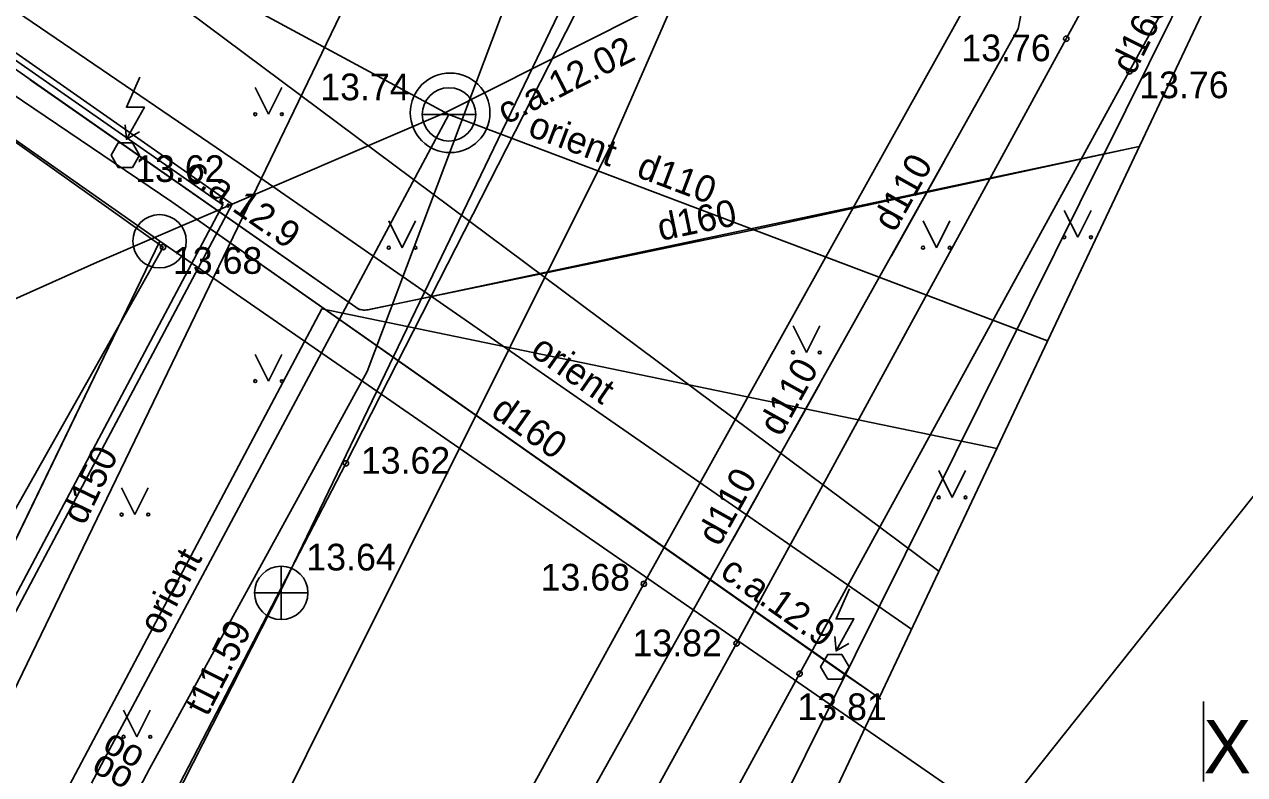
# Model space of a CAD drawing. Extents: x 503904 to 504094, y 304688 to 304960.
# Drawn here: x 504027.93 to 504050.77, y 304850.13 to 304864.18 of the extents above; entities that cross this region are included whole.
import ezdxf

# ---------------------------------------------------------------- set-up
doc = ezdxf.new("R2010")
doc.units = 0
for name, color, linetype in [('APGR_ELEM_####_####_#', 7, 'Continuous'), ('APGR_SARK_####_####_#', 7, 'Continuous'), ('APGS_ACRL_####_####_#', 7, 'Continuous'), ('APGS_ACRL_####_TKST_#', 7, 'Continuous'), ('APGS_VADP_ZSPR_####_#', 7, 'Continuous'), ('BUVE_GROD_VLIN_####_#', 7, 'Continuous'), ('CELI_CMAL_####_####_#', 7, 'Continuous'), ('CKOM_ELEM_####_####_#', 7, 'Continuous'), ('ELEK_ACRL_####_####_#', 7, 'Continuous'), ('ELEK_ACRL_####_TKST_#', 7, 'Continuous'), ('ELEK_VADP_NEDR_####_#', 7, 'Continuous'), ('ELEK_VADP_VSPR_####_#', 7, 'Continuous'), ('ELEK_VADP_VSPR_####_I', 7, 'Continuous'), ('ELEK_VADP_ZSPR_####_#', 7, 'Continuous'), ('ELEK_VADP_ZSPR_TKST_#', 7, 'Continuous'), ('ELEK_VADV_VSPR_####_#', 7, 'Continuous'), ('GAZE_VADP_VSP2_####_#', 7, 'Continuous'), ('GEOD_ELEM_####_####_#', 7, 'Continuous'), ('GEOD_KORD_####_TKST_#', 7, 'Continuous'), ('NORB_ZOGS_ZSTP_####_#', 7, 'Continuous'), ('RAMI_UZMR_####_####_#', 7, 'Continuous'), ('RELJ_AATZ_####_TKST_#', 7, 'Continuous'), ('RELJ_ELEM_####_####_#', 7, 'Continuous'), ('ROBZ_UZMR_####_####_#', 7, 'Continuous'), ('SAKK_IZVK_####_TKST_#', 7, 'Continuous'), ('SAKK_KKAN_####_####_#', 7, 'Continuous'), ('SAKT_VADP_KABE_####_#', 7, 'Continuous'), ('SKAN_ELEM_####_####_#', 7, 'Continuous'), ('SKAN_ELEM_PAST_TKST_#', 7, 'Continuous'), ('SKAN_VADP_PAST_####_#', 7, 'Continuous'), ('SKAN_VADP_PAST_####_I', 7, 'Continuous'), ('SKAN_VADP_PAST_TKST_#', 7, 'Continuous'), ('SKAN_VADP_PAST_TKST_I', 7, 'Continuous'), ('TERT_ELEM_####_####_#', 7, 'Continuous'), ('UDTK_ELEM_####_####_#', 7, 'Continuous'), ('UDTK_ELEM_####_TKST_#', 7, 'Continuous'), ('UDTK_VADP_NEDR_####_#', 7, 'Continuous'), ('UDTK_VADP_NEDR_TKST_#', 7, 'Continuous'), ('UDTK_VADP_UDEN_####_#', 7, 'Continuous'), ('UDTK_VADP_UDEN_TKST_#', 7, 'Continuous')]:
    doc.layers.add(name, color=color, linetype=linetype)

msp = doc.modelspace()

# ---------------------------------------------------------------- linework, layer by layer
at = {"layer": 'APGR_ELEM_####_####_#'}
msp.add_circle((504030.46, 304860.12), 0.5, dxfattribs=at)
at = {"layer": 'APGR_SARK_####_####_#'}
for p, q in [((503981.123, 304894.75), (504030.463, 304860.121)), ((504046.119, 304849.289), (504060.581, 304867.489)), ((504030.463, 304860.121), (503981.982, 304759.672))]:
    msp.add_line(p, q, dxfattribs=at)
at = {"layer": 'APGS_ACRL_####_####_#'}
for points in [[(504045.151, 304861.628), (504044.158, 304859.85)], [(504042.819, 304857.451), (504042.332, 304856.578)], [(504041.67, 304855.392), (504041.182, 304854.519)]]:
    msp.add_lwpolyline(points, dxfattribs=at)
at = {"layer": 'APGS_VADP_ZSPR_####_#'}
msp.add_lwpolyline([(504034.948, 304837.203), (504032.464, 304838.354), (504032.46, 304838.624), (504032.497, 304838.963), (504034.767, 304843.029), (504037.037, 304847.095), (504041.785, 304855.598), (504046.532, 304864.101), (504046.909, 304866.055), (504048.051, 304868.025), (504049.192, 304869.995), (504049.205, 304870.202), (504049.157, 304870.343), (504042.295, 304873.577), (504035.433, 304876.812), (504031.898, 304878.478), (504020.359, 304883.989), (504008.82, 304889.499), (504008.617, 304889.54), (504008.431, 304889.443), (504006.058, 304885.968)], dxfattribs=at)
at = {"layer": 'BUVE_GROD_VLIN_####_#'}
msp.add_circle((504035.898, 304862.527), 0.745, dxfattribs=at)
at = {"layer": 'CELI_CMAL_####_####_#'}
for points in [[(504043.505, 304874.98), (504041.235, 304870.26), (504033.948, 304855.96), (504026.066, 304840.762)], [(504032.161, 304840.294), (504039.525, 304853.703), (504045.705, 304864.823), (504050.845, 304874.537)], [(504032.559, 304836.774), (504041.261, 304852.587), (504047.431, 304863.915), (504052.724, 304873.608), (504051.009, 304874.521), (504050.882, 304874.598)], [(504054.623, 304874.25), (504048.611, 304863.3), (504042.44, 304852.018), (504033.541, 304835.699)]]:
    msp.add_lwpolyline(points, dxfattribs=at)
at = {"layer": 'CKOM_ELEM_####_####_#'}
for p, q in [((504029.841, 304862.031), (504030.082, 304862.17)), ((504043.122, 304852.447), (504043.363, 304852.586))]:
    msp.add_line(p, q, dxfattribs=at)
for points in [[(504030.09, 304863.193), (504029.841, 304862.63), (504030.177, 304862.63), (504029.841, 304862.031), (504029.819, 304862.301)], [(504043.371, 304853.609), (504043.122, 304853.046), (504043.458, 304853.046), (504043.122, 304852.447), (504043.1, 304852.717)]]:
    msp.add_lwpolyline(points, dxfattribs=at)
for points in [[(504029.685, 304861.501), (504029.951, 304861.501), (504030.084, 304861.731), (504029.951, 304861.962), (504029.685, 304861.962), (504029.552, 304861.731)], [(504042.966, 304851.917), (504043.232, 304851.917), (504043.365, 304852.147), (504043.232, 304852.378), (504042.966, 304852.378), (504042.833, 304852.147)]]:
    msp.add_lwpolyline(points, close=True, dxfattribs=at)
at = {"layer": 'ELEK_ACRL_####_####_#'}
for points in [[(504028.041, 304863.147), (504034.199, 304858.841), (504034.324, 304858.832), (504041.432, 304860.303), (504048.798, 304861.897)], [(504030.69, 304860.86), (504043.959, 304851.545)]]:
    msp.add_lwpolyline(points, dxfattribs=at)
at = {"layer": 'ELEK_VADP_NEDR_####_#'}
for points in [[(504021.775, 304819.315), (504017.104, 304821.576), (504012.433, 304823.836), (504012.326, 304823.953), (504012.339, 304824.112), (504013.491, 304826.283), (504014.644, 304828.454), (504016.196, 304831.379), (504017.749, 304834.304), (504019.433, 304837.477), (504021.118, 304840.651), (504023.847, 304845.791), (504025.258, 304848.45), (504028.54, 304854.632), (504031.821, 304860.814), (504022.135, 304867.596), (504012.45, 304874.378)], [(504012.365, 304874.256), (504022.005, 304867.531), (504031.646, 304860.805), (504025.265, 304848.775), (504019.402, 304837.719), (504017.809, 304834.715), (504016.163, 304831.611), (504014.517, 304828.507)]]:
    msp.add_lwpolyline(points, dxfattribs=at)
at = {"layer": 'ELEK_VADP_VSPR_####_#'}
for p, q in [((504034.133, 304858.885), (504026.897, 304863.949)), ((504048.798, 304861.895), (504035.37, 304859.048)), ((504035.37, 304859.048), (504034.366, 304858.838))]:
    msp.add_line(p, q, dxfattribs=at)
msp.add_arc((504034.305, 304859.131), 0.3, 235.0153, 281.835, dxfattribs=at)
at = {"layer": 'ELEK_VADP_VSPR_####_I'}
msp.add_lwpolyline([(504000, 304883.254), (504001.73, 304882.1), (504005.45, 304879.71), (504009.45, 304876.26), (504011.63, 304874.42), (504014.37, 304872.59), (504017, 304870.79), (504018.96, 304869.3), (504021.66, 304866.97), (504030.69, 304860.86), (504043.227, 304852.046), (504043.928, 304851.566)], dxfattribs=at)
at = {"layer": 'ELEK_VADP_ZSPR_####_#'}
msp.add_lwpolyline([(504002.84, 304883.907), (504013.238, 304874.636), (504017.897, 304871.307), (504022.559, 304867.983), (504028.527, 304863.916), (504031.948, 304861.583), (504040.554, 304855.614), (504044.535, 304852.853)], dxfattribs=at)
at = {"layer": 'ELEK_VADV_VSPR_####_#'}
msp.add_line((504017.859, 304874.234), (504045.046, 304853.939), dxfattribs=at)
at = {"layer": 'GAZE_VADP_VSP2_####_#'}
msp.add_lwpolyline([(504042.754, 304870.726), (504040.842, 304866.35), (504038.93, 304861.973), (504035.12, 304854.33), (504031.31, 304846.687), (504029.002, 304842.057), (504026.694, 304837.426), (504024.595, 304833.216), (504022.496, 304829.005), (504019.148, 304822.29), (504017.375, 304818.733), (504013.61, 304817.132), (504006.805, 304802.964), (504000, 304788.796), (503996.994, 304782.538), (503993.988, 304776.279), (503986.861, 304755.747)], dxfattribs=at)
at = {"layer": 'GEOD_ELEM_####_####_#'}
msp.add_line((504050, 304851.5), (504050, 304850), dxfattribs=at)
at = {"layer": 'NORB_ZOGS_ZSTP_####_#'}
msp.add_lwpolyline([(503994.545, 304885.205), (504006.615, 304876.836), (504018.641, 304868.474), (504030.525, 304860.01), (504021.686, 304844.338), (504014.326, 304831.324)], dxfattribs=at)
at = {"layer": 'RAMI_UZMR_####_####_#'}
msp.add_lwpolyline([(503923.253, 304801.015), (503981.982, 304759.672), (503995.48, 304748.813), (504027.75, 304817.255), (504060.02, 304885.696), (504048.875, 304885.773), (504036.803, 304888.853), (503994.536, 304908.303), (503981.123, 304894.75), (503978.518, 304892.436), (503950.886, 304846.726), (503923.253, 304801.015)], dxfattribs=at)
at = {"layer": 'RELJ_ELEM_####_####_#'}
for centre in [(504047.431, 304863.915), (504048.611, 304863.3), (504030.525, 304860.01), (504033.948, 304855.96), (504039.525, 304853.703), (504041.261, 304852.587), (504042.44, 304852.018)]:
    msp.add_circle(centre, 0.05, dxfattribs=at)
at = {"layer": 'ROBZ_UZMR_####_####_#'}
for points in [[(504052.953, 304844.812), (504048.85, 304847.4), (504030.463, 304860.121), (503981.123, 304894.75), (503968.011, 304904.031)], [(503976.684, 304743.679), (503981.982, 304759.672), (504030.463, 304860.121), (504048.85, 304847.4), (504035.67, 304821.93), (504026.069, 304827.305), (503995.067, 304763.071), (503986.854, 304740.353)]]:
    msp.add_lwpolyline(points, dxfattribs=at)
msp.add_lwpolyline([(503923.29, 304801.044), (503978.518, 304892.436), (503981.123, 304894.75), (504030.463, 304860.121), (503981.982, 304759.672)], close=True, dxfattribs=at)
at = {"layer": 'SAKK_KKAN_####_####_#'}
msp.add_lwpolyline([(504039.007, 304870.064), (504036.678, 304863.872), (504034.349, 304857.68), (504031.408, 304852.312), (504030.269, 304850.237), (504027.088, 304844.191), (504022.232, 304834.693), (504020.138, 304830.591), (504009.306, 304809.848), (504000, 304790.89), (503998.089, 304787.127), (503992.169, 304775.655), (503986.248, 304764.183), (503984.196, 304757.891)], dxfattribs=at)
at = {"layer": 'SAKT_VADP_KABE_####_#'}
msp.add_lwpolyline([(503984.36, 304757.759), (503986.696, 304764.614), (504000.633, 304794.323), (504014.571, 304824.033), (504017.941, 304829.488), (504018.377, 304830.312), (504025.72, 304844.17), (504033.498, 304858.852), (504046.129, 304856.235)], dxfattribs=at)
at = {"layer": 'SKAN_ELEM_####_####_#'}
for p, q in [((504032.738, 304853.033), (504032.738, 304854.033)), ((504032.238, 304853.533), (504033.238, 304853.533))]:
    msp.add_line(p, q, dxfattribs=at)
msp.add_circle((504032.738, 304853.533), 0.5, dxfattribs=at)
at = {"layer": 'SKAN_VADP_PAST_####_#'}
msp.add_lwpolyline([(504013.944, 304825.238), (504014.361, 304825.537), (504026.051, 304848.216), (504035.076, 304866.925), (504036.831, 304869.467)], dxfattribs=at)
at = {"layer": 'SKAN_VADP_PAST_####_I'}
msp.add_lwpolyline([(504023.783, 304835.985), (504032.733, 304853.578), (504047.208, 304883.667), (504054.39, 304883.114), (504058.648, 304882.787)], dxfattribs=at)
at = {"layer": 'TERT_ELEM_####_####_#'}
for p, q in [((504032.25, 304863), (504032.5, 304862.5)), ((504032.5, 304862.5), (504032.75, 304863)), ((504034.75, 304860.5), (504035, 304860)), ((504035, 304860), (504035.25, 304860.5)), ((504044.75, 304860.5), (504045, 304860)), ((504045, 304860), (504045.25, 304860.5)), ((504047.395, 304860.695), (504047.645, 304860.195)), ((504047.645, 304860.195), (504047.895, 304860.695)), ((504042.318, 304858.539), (504042.568, 304858.039)), ((504042.568, 304858.039), (504042.818, 304858.539)), ((504032.25, 304858), (504032.5, 304857.5)), ((504032.5, 304857.5), (504032.75, 304858)), ((504045.045, 304855.823), (504045.295, 304855.323)), ((504045.295, 304855.323), (504045.545, 304855.823)), ((504029.75, 304855.5), (504030, 304855)), ((504030, 304855), (504030.25, 304855.5)), ((504029.787, 304851.338), (504030.037, 304850.838)), ((504030.037, 304850.838), (504030.287, 304851.338))]:
    msp.add_line(p, q, dxfattribs=at)
for centre, radius in [((504032.25, 304862.5), 0.028), ((504032.75, 304862.5), 0.0263), ((504034.75, 304860), 0.028), ((504035.25, 304860), 0.0263), ((504044.75, 304860), 0.028), ((504045.25, 304860), 0.0263), ((504047.394, 304860.195), 0.028), ((504047.894, 304860.195), 0.0263), ((504042.317, 304858.038), 0.028), ((504042.817, 304858.038), 0.0263), ((504032.25, 304857.5), 0.028), ((504032.75, 304857.5), 0.0263), ((504045.045, 304855.322), 0.028), ((504045.545, 304855.322), 0.0263), ((504029.75, 304855), 0.028), ((504030.25, 304855), 0.0263), ((504029.787, 304850.838), 0.028), ((504030.287, 304850.838), 0.0263)]:
    msp.add_circle(centre, radius, dxfattribs=at)
at = {"layer": 'UDTK_ELEM_####_####_#'}
msp.add_line((504035.377, 304862.497), (504036.377, 304862.497), dxfattribs=at)
msp.add_circle((504035.877, 304862.497), 0.5, dxfattribs=at)
at = {"layer": 'UDTK_VADP_NEDR_####_#'}
msp.add_lwpolyline([(504018.286, 304854.806), (504025.161, 304857.88), (504029.291, 304859.726), (504035.8, 304862.529), (504046.496, 304867.919), (504053.241, 304871.318)], dxfattribs=at)
at = {"layer": 'UDTK_VADP_UDEN_####_#'}
for points in [[(504035.876, 304862.497), (503979.246, 304893.082)], [(504052.599, 304884.688), (504054.563, 304874.709), (504047.684, 304860.837), (504037.414, 304840.144), (504031.385, 304827.996), (504014.788, 304793.579), (504000, 304762.914), (503998.944, 304760.723), (503997.887, 304758.532), (503994.035, 304750.096), (503993.994, 304750.008)], [(504035.876, 304862.497), (503981.246, 304760.191)], [(504035.876, 304862.497), (504047.081, 304858.255)]]:
    msp.add_lwpolyline(points, dxfattribs=at)

# ---------------------------------------------------------------- texts
at = {"layer": 'APGS_ACRL_####_TKST_#'}
for rotation, p in [(60.8314, (504044.221, 304860.27)), (60.8452, (504042.084, 304856.442)), (60.7952, (504040.934, 304854.384))]:
    msp.add_text('d110', height=0.5, rotation=rotation, dxfattribs=at).set_placement(p)
at = {"layer": 'ELEK_ACRL_####_TKST_#'}
for s, rotation, p in [('c.a.12.9', 325.0345, (504030.913, 304861.322)), ('d160', 11.6967, (504039.837, 304860.126)), ('d160', 324.931, (504036.637, 304856.868)), ('c.a.12.9', 324.931, (504040.925, 304853.858))]:
    msp.add_text(s, height=0.5, rotation=rotation, dxfattribs=at).set_placement(p)
at = {"layer": 'ELEK_VADP_ZSPR_TKST_#'}
msp.add_text('orient', height=0.5, rotation=325.2554, dxfattribs=at).set_placement((504037.375, 304858.001))
at = {"layer": 'GEOD_KORD_####_TKST_#'}
msp.add_text('X=304850', height=1, dxfattribs=at).set_placement((504050, 304850.15))
at = {"layer": 'RELJ_AATZ_####_TKST_#'}
for s, p in [(' 13.76', (504045.282, 304863.493)), (' 13.76', (504048.611, 304862.8)), (' 13.62', (504029.818, 304861.231)), (' 13.68', (504030.525, 304859.51)), (' 13.62', (504034.042, 304855.765)), (' 13.68', (504037.407, 304853.577)), (' 13.82', (504039.127, 304852.345)), (' 13.81', (504042.213, 304851.15))]:
    msp.add_text(s, height=0.5, dxfattribs=at).set_placement(p)
at = {"layer": 'SAKK_IZVK_####_TKST_#'}
for p in [(504029.368, 304850.589), (504029.166, 304850.199)]:
    msp.add_text('oo', height=0.5, rotation=331.4931, dxfattribs=at).set_placement(p)
at = {"layer": 'SKAN_ELEM_PAST_TKST_#'}
msp.add_text('13.64', height=0.5, dxfattribs=at).set_placement((504033.208, 304853.953))
at = {"layer": 'SKAN_VADP_PAST_TKST_#'}
msp.add_text('d150', height=0.5, rotation=64.2479, dxfattribs=at).set_placement((504029.052, 304854.782))
at = {"layer": 'SKAN_VADP_PAST_TKST_I'}
msp.add_text('t11.59', height=0.5, rotation=63.035, dxfattribs=at).set_placement((504031.355, 304851.2))
at = {"layer": 'UDTK_ELEM_####_TKST_#'}
msp.add_text('13.74', height=0.5, dxfattribs=at).set_placement((504033.468, 304862.762))
at = {"layer": 'UDTK_VADP_NEDR_TKST_#'}
msp.add_text('c.a.12.02', height=0.5, rotation=26.7456, dxfattribs=at).set_placement((504036.945, 304862.299))
at = {"layer": 'UDTK_VADP_UDEN_TKST_#'}
for s, rotation, p in [('d160', 63.6045, (504048.695, 304863.212)), ('orient', 339.2649, (504037.329, 304862.107)), ('d110', 339.2649, (504039.364, 304861.337)), ('orient', 61.8985, (504030.482, 304852.714))]:
    msp.add_text(s, height=0.5, rotation=rotation, dxfattribs=at).set_placement(p)

doc.saveas('drawing.dxf')
